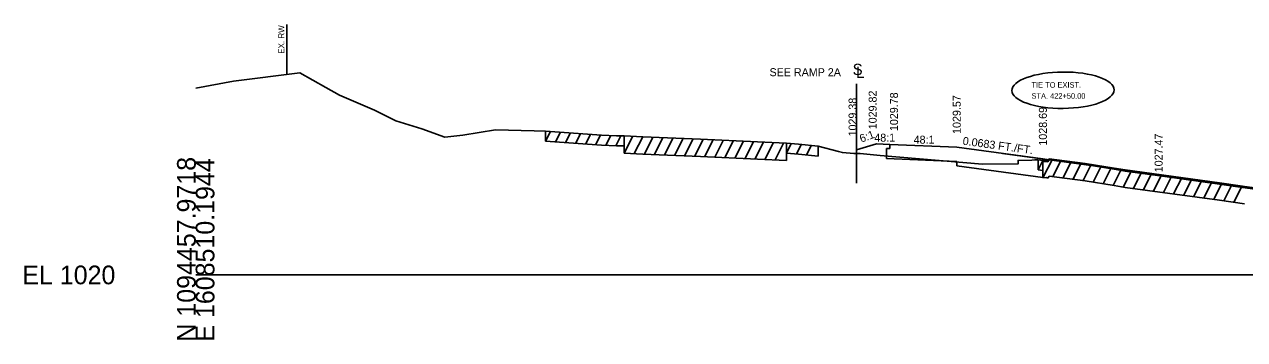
# Model space of a CAD drawing. Extents: x -26 to 1614813, y -18 to 1100051.
# Drawn here: x 3974.3 to 4157.3, y 8990.3 to 9037.6 of the extents above; entities that cross this region are included whole.
import ezdxf

# ---------------------------------------------------------------- set-up
doc = ezdxf.new("R2010")
doc.units = 0
for name, color, linetype in [('RD_EX_Misc', 7, 'Continuous'), ('RD_GPK_XS_Cell', 7, 'Continuous'), ('RD_Sketch1', 7, 'Continuous'), ('RD_Sketch10', 7, 'Continuous'), ('RD_XS_Base', 7, 'Continuous'), ('RD_XS_EarthShd', 7, 'Continuous'), ('RD_XS_ExGround', 7, 'Continuous'), ('RD_XS_ExPaveRet', 7, 'Continuous'), ('RD_XS_ExRW', 7, 'Continuous'), ('RD_XS_MatchLine', 7, 'Continuous'), ('RD_XS_Milling', 7, 'Continuous'), ('RD_XS_Pave', 7, 'Continuous'), ('RD_XS_PaveOvlay', 7, 'Continuous'), ('RD_XS_PaveShd', 7, 'Continuous'), ('RD_XS_TX_Elev_PR', 7, 'Continuous'), ('RD_XS_TX_MatchLine', 7, 'Continuous'), ('RD_XS_TX_Notes', 7, 'Continuous'), ('RD_XS_TX_ShdSlope', 7, 'Continuous'), ('RD_XS_TX_Slope', 7, 'Continuous')]:
    doc.layers.add(name, color=color, linetype=linetype)

msp = doc.modelspace()

# ---------------------------------------------------------------- linework, layer by layer
at = {"layer": 'RD_EX_Misc'}
for p, q in [((4052.45, 9020.05), (4052.45, 9021.55)), ((4052.45, 9020.05), (4060.87, 9019.47)), ((4060.87, 9019.47), (4063.08, 9019.35)), ((4063.08, 9019.35), (4064.26, 9019.36)), ((4064.26, 9020.86), (4064.26, 9019.36)), ((4088.57, 9018.26), (4088.57, 9019.76)), ((4093.35, 9019.3), (4093.35, 9017.8)), ((4088.57, 9018.26), (4088.58, 9018.26)), ((4088.58, 9018.26), (4090.39, 9018.08)), ((4090.39, 9018.08), (4093.35, 9017.8)), ((4126.33, 9015.75), (4126.33, 9017.25)), ((4126.33, 9015.75), (4127.04, 9015.64)), ((4127.04, 9017.14), (4127.04, 9015.64))]:
    msp.add_line(p, q, dxfattribs=at)
at = {"layer": 'RD_GPK_XS_Cell'}
msp.add_line((4000, 9000), (4175, 9000), dxfattribs=at)
at = {"layer": 'RD_Sketch1'}
for p, q in [((4052.45, 9020.05), (4053.18, 9021.5)), ((4053.96, 9019.95), (4054.69, 9021.4)), ((4055.47, 9019.85), (4056.2, 9021.3)), ((4056.98, 9019.74), (4057.7, 9021.19)), ((4058.48, 9019.64), (4059.21, 9021.09)), ((4059.99, 9019.53), (4060.72, 9020.98)), ((4061.5, 9019.44), (4062.24, 9020.9)), ((4063.01, 9019.36), (4063.76, 9020.85)), ((4088.57, 9018.26), (4089.29, 9019.69)), ((4090.08, 9018.11), (4090.8, 9019.54)), ((4091.59, 9017.96), (4092.31, 9019.4)), ((4126.33, 9015.75), (4127.03, 9017.14))]:
    msp.add_line(p, q, dxfattribs=at)
at = {"layer": 'RD_Sketch10'}
for p, q in [((4121, 9018.22), (4145, 9014.94)), ((4145, 9014.94), (4157, 9013.3))]:
    msp.add_line(p, q, dxfattribs=at)
at = {"layer": 'RD_XS_Base'}
for p, q in [((4104.11, 9019.56), (4104.11, 9018.93)), ((4103.61, 9018.95), (4103.61, 9017.45)), ((4104.11, 9018.93), (4103.61, 9018.95)), ((4114.12, 9017.01), (4103.61, 9017.45)), ((4114.12, 9017.01), (4114.12, 9016.37)), ((4127.04, 9014.6), (4114.12, 9016.37))]:
    msp.add_line(p, q, dxfattribs=at)
at = {"layer": 'RD_XS_EarthShd'}
for p, q in [((4102.11, 9019.64), (4099.1, 9018.76)), ((4104.11, 9019.56), (4102.11, 9019.64))]:
    msp.add_line(p, q, dxfattribs=at)
at = {"layer": 'RD_XS_ExGround'}
msp.add_lwpolyline([(4000, 9028.02), (4005.67, 9029.03), (4015.59, 9030.28), (4019.52, 9028.1), (4021.56, 9026.95), (4026.79, 9024.69), (4030, 9023.09), (4033.91, 9021.88), (4037.37, 9020.66), (4040.03, 9020.93), (4044.95, 9021.73), (4050.73, 9021.6), (4052.45, 9021.55), (4060.87, 9020.97), (4063.08, 9020.85), (4064.26, 9020.86), (4067.04, 9020.71), (4075.71, 9020.33), (4084.23, 9019.93), (4088.58, 9019.76), (4090.39, 9019.58), (4093.35, 9019.3), (4096.39, 9018.52), (4096.98, 9018.34), (4098.68, 9018.2), (4099.66, 9018.18), (4102.62, 9017.88), (4117.99, 9016.61), (4123.32, 9016.63), (4123.32, 9017.16), (4125.39, 9017.22), (4125.82, 9017.23), (4126.33, 9017.25), (4127.04, 9017.14), (4127.52, 9017.19), (4127.76, 9017.13), (4127.99, 9017.42), (4129.12, 9017.27), (4133.39, 9016.7), (4137.71, 9016), (4139.37, 9015.73), (4153.52, 9013.79), (4157.29, 9013.26), (4162.93, 9012.5)], dxfattribs=at)
at = {"layer": 'RD_XS_ExPaveRet'}
for p, q in [((4064.26, 9018.26), (4064.26, 9020.86)), ((4064.26, 9018.26), (4065.54, 9020.79)), ((4065.77, 9018.18), (4067.04, 9020.71)), ((4067.28, 9018.1), (4068.56, 9020.65)), ((4068.78, 9018.04), (4070.06, 9020.58)), ((4070.29, 9017.97), (4071.57, 9020.52)), ((4071.8, 9017.91), (4073.08, 9020.45)), ((4073.31, 9017.84), (4074.58, 9020.38)), ((4074.81, 9017.77), (4076.09, 9020.32)), ((4076.32, 9017.71), (4077.6, 9020.25)), ((4077.83, 9017.63), (4079.1, 9020.17)), ((4079.34, 9017.56), (4080.61, 9020.1)), ((4080.84, 9017.49), (4082.12, 9020.03)), ((4082.35, 9017.42), (4083.63, 9019.96)), ((4083.86, 9017.35), (4085.14, 9019.9)), ((4085.36, 9017.29), (4086.64, 9019.84)), ((4086.87, 9017.23), (4088.15, 9019.77)), ((4088.57, 9019.76), (4088.57, 9017.16)), ((4064.26, 9018.26), (4067.04, 9018.11)), ((4064.26, 9018.26), (4064.26, 9018.26)), ((4067.04, 9018.11), (4075.71, 9017.73)), ((4075.71, 9017.73), (4084.23, 9017.33)), ((4084.23, 9017.33), (4088.57, 9017.16)), ((4127.04, 9014.54), (4128.46, 9017.36)), ((4127.04, 9014.54), (4127.04, 9017.14)), ((4128.55, 9014.74), (4129.78, 9017.18)), ((4130.06, 9014.54), (4131.28, 9016.98)), ((4131.57, 9014.34), (4132.79, 9016.78)), ((4133.07, 9014.14), (4134.29, 9016.55)), ((4134.58, 9013.91), (4135.79, 9016.31)), ((4136.09, 9013.66), (4137.3, 9016.07)), ((4137.59, 9013.42), (4138.8, 9015.82)), ((4139.1, 9013.18), (4140.32, 9015.6)), ((4127.04, 9014.54), (4127.52, 9014.59)), ((4127.04, 9014.54), (4127.04, 9014.54)), ((4127.52, 9014.59), (4127.76, 9014.53)), ((4127.76, 9014.53), (4127.99, 9014.82)), ((4127.99, 9014.82), (4129.12, 9014.67)), ((4129.12, 9014.67), (4133.39, 9014.1)), ((4133.39, 9014.1), (4137.71, 9013.4)), ((4140.61, 9012.96), (4141.83, 9015.4)), ((4142.12, 9012.76), (4143.34, 9015.19)), ((4143.62, 9012.55), (4144.85, 9014.98)), ((4145.13, 9012.34), (4146.35, 9014.77)), ((4146.64, 9012.14), (4147.86, 9014.57)), ((4148.15, 9011.93), (4149.37, 9014.36)), ((4149.65, 9011.72), (4150.88, 9014.15)), ((4151.16, 9011.51), (4152.38, 9013.95)), ((4152.67, 9011.31), (4153.89, 9013.74)), ((4137.71, 9013.4), (4139.37, 9013.13)), ((4139.37, 9013.13), (4153.52, 9011.19)), ((4154.18, 9011.1), (4155.39, 9013.52)), ((4155.68, 9010.88), (4156.9, 9013.31)), ((4153.52, 9011.19), (4157.29, 9010.66)), ((4157.29, 9010.66), (4157.29, 9010.66))]:
    msp.add_line(p, q, dxfattribs=at)
at = {"layer": 'RD_XS_ExRW'}
msp.add_line((4013.64, 9037.55), (4013.64, 9030.04), dxfattribs=at)
at = {"layer": 'RD_XS_MatchLine'}
msp.add_line((4099.1, 9018.19), (4099.1, 9018.76), dxfattribs=at)
at = {"layer": 'RD_XS_Milling'}
for p, q in [((4127.04, 9017.14), (4127.04, 9016.98)), ((4127.04, 9016.98), (4127.52, 9017.02)), ((4127.04, 9016.98), (4127.04, 9016.98)), ((4127.52, 9017.02), (4127.76, 9016.96)), ((4127.76, 9016.96), (4127.99, 9017.25)), ((4127.99, 9017.25), (4129.12, 9017.1)), ((4129.12, 9017.1), (4133.39, 9016.53)), ((4133.39, 9016.53), (4137.71, 9015.83)), ((4137.71, 9015.83), (4139.37, 9015.57)), ((4139.37, 9015.57), (4145, 9014.79)), ((4145, 9014.94), (4145, 9014.77)), ((4145, 9014.79), (4153.52, 9013.62)), ((4153.52, 9013.62), (4157, 9013.13)), ((4157, 9013.3), (4157, 9013.13))]:
    msp.add_line(p, q, dxfattribs=at)
at = {"layer": 'RD_XS_Pave'}
for p, q in [((4127.04, 9017.38), (4114.12, 9019.14)), ((4127.99, 9017.25), (4127.04, 9017.38))]:
    msp.add_line(p, q, dxfattribs=at)
at = {"layer": 'RD_XS_PaveOvlay'}
for p, q in [((4127.76, 9017.13), (4127.99, 9017.42)), ((4127.99, 9017.42), (4129.12, 9017.27)), ((4127.04, 9017.14), (4127.52, 9017.19)), ((4127.04, 9017.14), (4127.04, 9017.14)), ((4127.04, 9017.14), (4127.04, 9016.98)), ((4127.52, 9017.19), (4127.76, 9017.13)), ((4129.12, 9017.27), (4133.39, 9016.7)), ((4133.39, 9016.7), (4137.71, 9016)), ((4137.71, 9016), (4139.37, 9015.73)), ((4139.37, 9015.73), (4145, 9014.96)), ((4145, 9014.96), (4153.52, 9013.79)), ((4153.52, 9013.79), (4157, 9013.3)), ((4157, 9013.3), (4157, 9013.13))]:
    msp.add_line(p, q, dxfattribs=at)
at = {"layer": 'RD_XS_PaveShd'}
for p, q in [((4114.12, 9019.14), (4104.11, 9019.56)), ((4157, 9013.13), (4178.35, 9010.21))]:
    msp.add_line(p, q, dxfattribs=at)
at = {"layer": 'RD_XS_TX_MatchLine'}
for p, q in [((4099.1, 9018.76), (4099.1, 9028.65)), ((4099.1, 9013.76), (4099.1, 9018.76))]:
    msp.add_line(p, q, dxfattribs=at)
at = {"layer": 'RD_XS_TX_Notes'}
msp.add_ellipse((4130.06, 9027.69), major_axis=(7.68, 0.05), ratio=0.355189, dxfattribs=at)

# ---------------------------------------------------------------- texts
at = {"layer": 'RD_GPK_XS_Cell'}
for s, p in [('N 1094457.9718', (4000, 8990)), ('E 1608510.1944', (4002.8, 8990))]:
    msp.add_text(s, height=2.8, rotation=90, dxfattribs=at).set_placement(p)
msp.add_text('EL 1020', height=2.8, dxfattribs=at).set_placement((3974, 8998.6))
at = {"layer": 'RD_Sketch10'}
msp.add_text(' 1027.47', height=1.2, rotation=90, dxfattribs=at).set_placement((4145, 9014.94))
at = {"layer": 'RD_XS_ExRW'}
msp.add_text('EX. RW', height=0.9, rotation=90, dxfattribs=at).set_placement((4013.28, 9033.15))
at = {"layer": 'RD_XS_TX_Elev_PR'}
for s, p in [('1029.82', (4102.11, 9021.83)), ('1029.78', (4105.31, 9021.56)), ('1029.57', (4114.72, 9021.14)), ('1029.38', (4099.1, 9020.76)), ('1028.69', (4127.64, 9019.38))]:
    msp.add_text(s, height=1.2, rotation=90, dxfattribs=at).set_placement(p)
at = {"layer": 'RD_XS_TX_MatchLine'}
for s, p in [('S', (4098.51, 9029.97)), ('L', (4099.03, 9029.53))]:
    msp.add_text(s, height=1.68, dxfattribs=at).set_placement(p)
at = {"layer": 'RD_XS_TX_Notes'}
for s, height, p in [('SEE RAMP 2A', 1.2, (4086.05, 9029.79)), ('TIE TO EXIST. ', 0.8333, (4125.34, 9028.07)), ('STA. 422+50.00', 0.8333, (4125.34, 9026.41))]:
    msp.add_text(s, height=height, dxfattribs=at).set_placement(p)
at = {"layer": 'RD_XS_TX_ShdSlope'}
for s, rotation, p in [('6:1', 20.0953, (4099.81, 9019.82)), ('48:1', 0.171, (4101.76, 9019.97)), ('48:1', 0.171, (4107.66, 9019.67))]:
    msp.add_text(s, height=1.2, rotation=rotation, dxfattribs=at).set_placement(p)
at = {"layer": 'RD_XS_TX_Slope'}
msp.add_text('0.0683 FT./FT.', height=1.2, rotation=352.2215, dxfattribs=at).set_placement((4114.96, 9019.53))

doc.saveas('drawing.dxf')
